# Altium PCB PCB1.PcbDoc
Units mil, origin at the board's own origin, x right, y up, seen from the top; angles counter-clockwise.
Board outline 984.25 x 984.25 mil, 2 copper layers (Top Layer, Bottom Layer); 59 components, 54 nets, 230 pads, 136 vias.
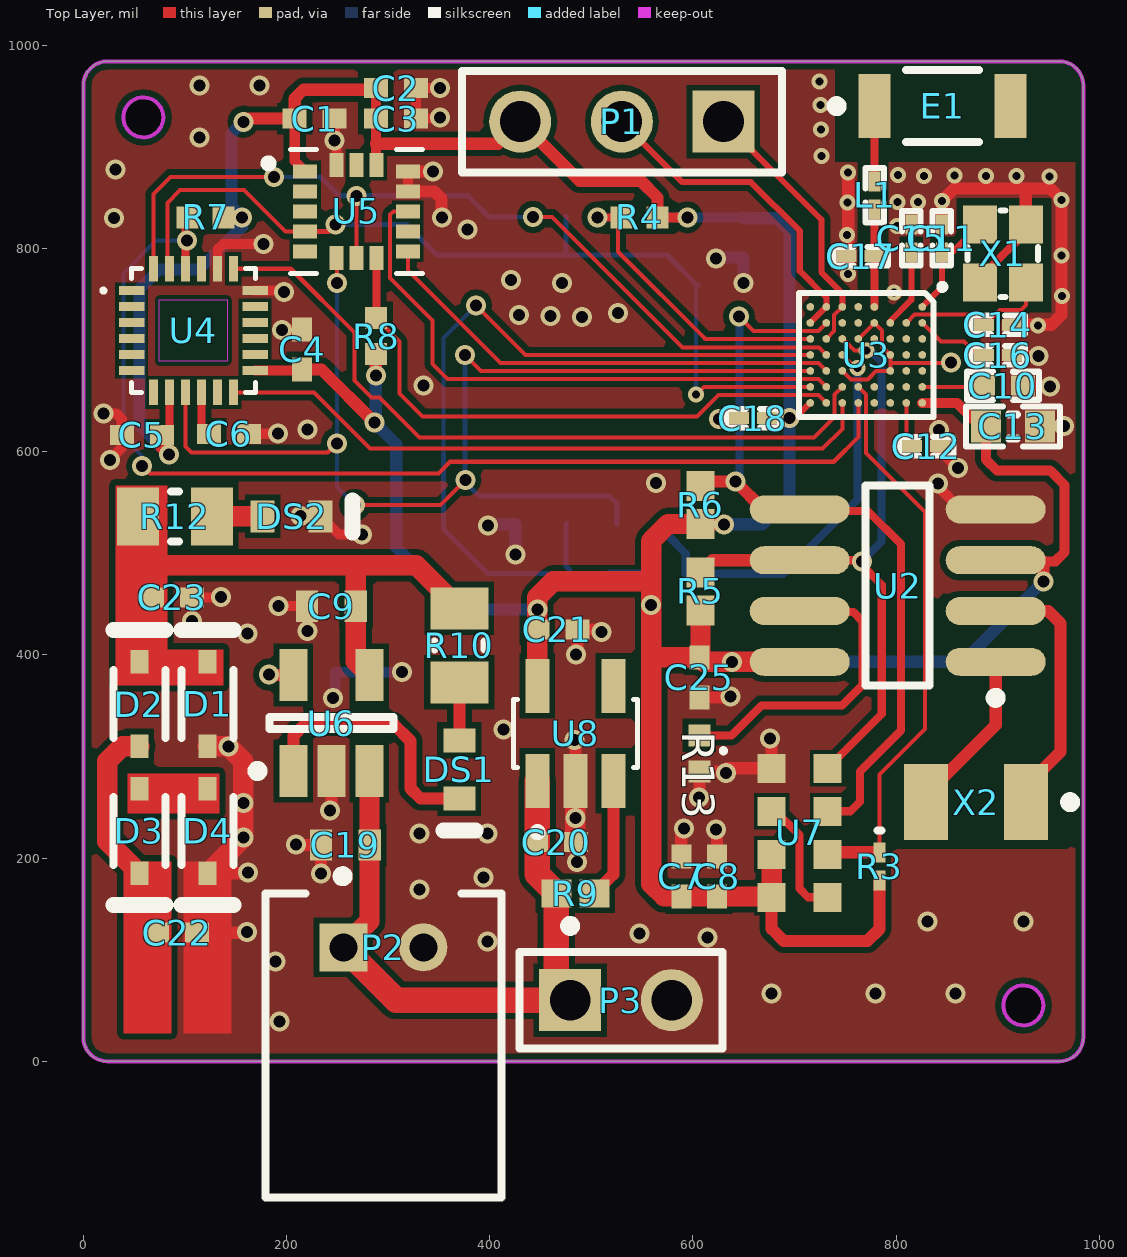
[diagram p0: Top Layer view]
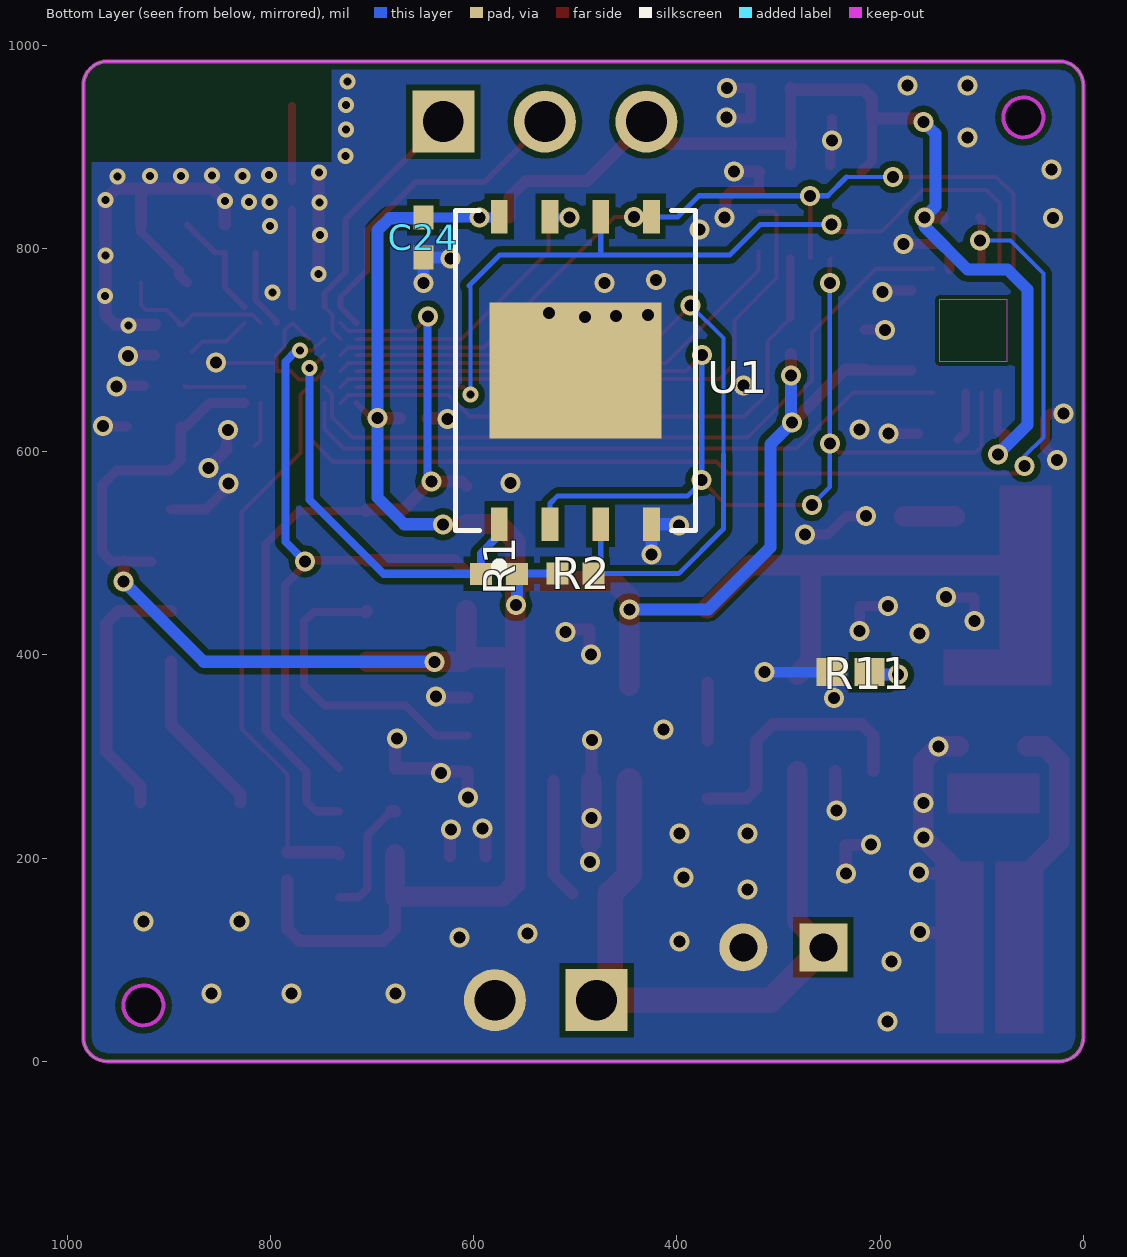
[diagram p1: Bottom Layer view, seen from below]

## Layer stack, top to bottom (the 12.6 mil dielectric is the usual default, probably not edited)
Top Solder: solder mask 0.4, Solder Resist, Dk 3.5
Top Layer: signal copper 1.4
Dielectric1: dielectric 12.6, FR-4, Dk 4.8
Bottom Layer: signal copper 1.4
Bottom Solder: solder mask 0.4, Solder Resist, Dk 3.5

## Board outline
0,23.62 0,960.63 cw(c23.62,960.63) 23.62,984.25 960.63,984.25 cw(c960.63,960.63) 984.25,960.63 984.25,23.62 cw(c960.63,23.62) 960.63,0 23.62,0 cw(c23.62,23.62)
cut-out: 905.51,55.12 ccw(c925.2,55.12) 925.2,35.43 ccw(c925.2,55.12) 944.88,55.12 ccw(c925.2,55.12) 925.2,74.8 ccw(c925.2,55.12)
cut-out: 59.06,909.45 cw(c59.06,929.13) 39.37,929.13 cw(c59.06,929.13) 59.06,948.82 cw(c59.06,929.13) 78.74,929.13 cw(c59.06,929.13)

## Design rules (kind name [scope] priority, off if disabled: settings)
Clearance Clearance_1 [InComponentClass('p')] p1: gap=3.94
Clearance [All] p2: gap=5.91
PolygonConnect [All] p1: connectstyle=Direct reliefconductorwidth=10 reliefentries=4 polygonreliefangle="90 Angle" airgapwidth=10
RoutingVias [All] p1: holewidth=11.81 width=19.68 viastyle="Through Hole" minholewidth=11.81 minwidth=19.68 maxholewidth=11.81 maxwidth=19.68
SilkToSolderMaskClearance SilkscreenOverComponentPads [IsPad] p1: minsilkscreentomaskgap=10 clearancetoexposedcopper=TRUE
SolderMaskExpansion [All] p1: expansion=4
Width [All] p1: maxlimit=1000 minlimit=4 preferedwidth=10
29 further rules are at their usual default settings.

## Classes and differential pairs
component class p: U3 U4 U5 U7
component class "SimPL_IMU_v1_1 _OCT31(2)": C10 C11 C12 C13 C14 C15 C16 C17 C18 C24 C25 C? E1 L1 P1 R1 R2 R4 R5 R6 R13 U1 U2 U3 X1 X2
component class "SimPL_IMU_v1_0 _OCT31(2)": C1 C2 C3 C4 C5 C6 C7 C8 C9 C19 C20 C21 C22 C23 D1 D2 D3 D4 DS1 DS2 P2 P3 R3 R7 R8 R9 R10 R11 R12 U4 U5 U6 U7 U8

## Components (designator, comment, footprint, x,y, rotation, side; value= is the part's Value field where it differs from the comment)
C1 "0.1uF" 0402 227.72,927.87 r0 top
C2 "0.1uF" 0402 307.72,957.87 r0 top
C3 "1.0uF" 0402 307.72,927.87 r0 top
C4 "0.1uF" 0402 215.39,700.79 r90 top
C5 "0.1uF" 0402 57.48,616.54 r180 top
C6 "0.1uF" 0402 143.31,617.72 r0 top
C7 "0.1uF" 0402 588.52,181.99 r90 top
C8 "2.2uF" 0402 623.52,181.99 r90 top
C9 "4.7uF" CAPC1005X65X10ML15 244.17,448.03 r0 top
C10 "1.0µF" CAPC1005X04L 905,665 r180 top
C11 "12pF" CAPC0603X03L 845,810 r270 top
C12 "100nF" CAPC0603X03L 829.53,605.51 r0 top
C13 "4.7µF" CAPC1608X06L 915,625 r0 top
C14 "12pF" CAPC0603X03L 900,725 r180 top
C15 "100pF" CAPC0603X03L 815,810 r90 top
C16 "100pF" CAPC0603X03L 900,695 r180 top
C17 "1.0pF" CAPC0603X03L 764.96,792.52 r0 top
C18 "100nF" CAPC0603X03L 659.06,633.07 r180 top
C19 "4.7uF" CAPC1005X65X10ML15 257.87,212.99 r0 top
C20 "1uF" 0402 465.35,215.75 r0 top
C21 "1uF" 0402 466.54,425.2 r0 top
C22 "6.8nF" 0402 92.4,126.65 r0 top
C23 "220uF" 0402 87.4,456.65 r0 top
C24 "1.0uF" 0402 649.61,811.02 r270 bottom
C25 "2.2uF" 0402 606.3,377.95 r270 top
D1 "1N4148WS" DIOD-SOD323-2-A_V 122.4,351.65 r90 top
D2 "1N4148WS" DIOD-SOD323-2-A_V 55.16,351.65 r90 top
D3 "1N4148WS" DIOD-SOD323-2-A_V 55.16,226.77 r270 top
D4 "1N4148WS" DIOD-SOD323-2-A_V 122.4,226.65 r270 top
DS1 "red LED" VISH-TLMS1000_V 370.08,287.4 r270 top
DS2 "red LED" VISH-TLMS1000_V 205,536.5 r0 top
E1 "2450AT18A100E" JT-2450AT18A100-2_V 845.67,940.16 r0 top
L1 "3.3nH" INDC0603X03L 778.74,852.36 r90 top
P1 "3pin header" SMTC-TSW-103-07-X-S 630,925 r180 top
P2 "Battery Header" JST-S2B-PH-K-S_V 295.28,15.75 r0 top
P3 "2pin header" AMPH-68000-102HLF_V 529.13,60.24 r0 top
R1 "10k" RESC1005X40X25NL05T05 575.2,479.92 r180 bottom
R2 "10k" RESC1005X40X25NL05T05 500,480 r0 bottom
R3 "8.2k" 0603 783.52,191.99 r270 top
R4 "10k" RESC1005X40X25NL05T05 547.24,830.71 r0 top
R5 "2.2K" RESC1005X40X25ML10T10 607.36,462.64 r270 top
R6 "2.2K" RESC1005X40X25ML10T10 607.36,547.64 r270 top
R7 "10k" RESC1005X40X25NL05T05 120.39,830.79 r0 top
R8 "10k" RESC1005X40X25NL05T05 288.19,713.78 r270 top
R9 "2.2K" RESC1005X40X25ML10T10 484.25,165.35 r180 top
R10 "330" RESC2013X50X30NL20T20 370.08,409.45 r90 top
R11 "2.2K" RESC1005X40X25ML10T10 229.17,383.03 r180 bottom
R12 "330" RESC2013X50X30NL20T20 90,536.5 r180 top
R13 "1k" RESC1005X40X25NL05T05 606.3,303.15 r90 top
U1 "MT25QL256ABA1EW9-0SIT" *SON127P600X800X80-9N 500,680 r90 bottom
U2 "DS1388Z-33+T&R" S8+4_M 801.54,468.23 r180 top
U3 "nRF52832-CIAA" BGA50C40P7X8_295X322X50 770.63,695.35 r270 top
U4 "ICM-20649" *QFN40P300X300X95-24N 108.27,719.29 r0 top
U5 "ADXL372BCCZ-RL7" *PQFN50P322X300X114-16N 268.78,836.57 r0 top
U6 "MCP73831T-2ATI/OT" SOT-23-OT5_M 244.17,333.03 r90 top
U7 "VCNL4040M3OE" *VISHAY_VCNL4040_4X2X1.1 705,225 r0 top
U8 "AP2112K-3.3TRG1" *SOT95P285X140-5N 484.25,322.83 r90 top
X1 "32MHz" BT-XTAL_2016 905,795 r90 top
X2 "32.768KHz-T" ABRA-ABS07-2_V 878.74,255.12 r180 top

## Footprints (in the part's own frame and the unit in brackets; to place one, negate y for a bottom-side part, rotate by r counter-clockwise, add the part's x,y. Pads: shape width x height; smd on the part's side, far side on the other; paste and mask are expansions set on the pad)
0402 [mm] "Chip Capacitor, Body 1.0x0.5mm, IPC High Density"
  rect 0.6x0.5 smd: 1(-0.5,0) 2(0.5,0)
  body extent -0.55,-0.3 0.55,0.3, height 1.3
0603 [mm] "Chip Inductor, Body 0.6x0.3mm, IPC High Density"
  rect 0.5x0.3 smd: 1(-0.35,0) 2(0.35,0)
  silkscreen extent -0.9,-0.05 -0.9,0.05, body extent -0.33,-0.18 0.33,0.18, height 0.55
*PQFN50P322X300X114-16N [mm]
  rect 0.6x0.35 smd: 1(-1.285,1) 2(-1.285,0.5) 3(-1.285,0) 4(-1.285,-0.5) 5(-1.285,-1) 9(1.285,-1) 10(1.285,-0.5) 11(1.285,0) 12(1.285,0.5) 13(1.285,1)
  rect 0.35x0.6 smd: 6(-0.5,-1.165) 7(0,-1.165) 8(0.5,-1.165) 14(0.5,1.165) 15(0,1.165) 16(-0.5,1.165)
  silkscreen extent -2.3,-1.55 1.65,1.55
*QFN40P300X300X95-24N [mm]
  rect 0.64x0.22 smd: 1(-1.545,1) 2(-1.545,0.6) 3(-1.545,0.2) 4(-1.545,-0.2) 5(-1.545,-0.6) 6(-1.545,-1) 13(1.545,-1) 14(1.545,-0.6) 15(1.545,-0.2) 16(1.545,0.2) 17(1.545,0.6) 18(1.545,1)
  rect 0.22x0.64 smd: 7(-1,-1.545) 8(-0.6,-1.545) 9(-0.2,-1.545) 10(0.2,-1.545) 11(0.6,-1.545) 12(1,-1.545) 19(1,1.545) 20(0.6,1.545) 21(0.2,1.545) 22(-0.2,1.545) 23(-0.6,1.545) 24(-1,1.545)
  Keep-Out Layer region: -0.85,0.77 0.85,0.77 0.85,-0.77 -0.85,-0.77
  Keep-Out Layer region: -0.85,0.77 0.85,0.77 0.85,-0.77 -0.85,-0.77
  Keep-Out Layer region: -0.85,0.77 0.85,0.77 0.85,-0.77 -0.85,-0.77
  Keep-Out Layer region: -0.85,0.77 0.85,0.77 0.85,-0.77 -0.85,-0.77
  Keep-Out Layer region: -0.85,0.77 0.85,0.77 0.85,-0.77 -0.85,-0.77
  Keep-Out Layer region: -0.85,0.77 0.85,0.77 0.85,-0.77 -0.85,-0.77
  silkscreen extent -2.3,-1.55 1.55,1.55
*SON127P600X800X80-9N [mm]
  rect 0.84x0.42 smd: 1(-3.845,1.905) 2(-3.845,0.635) 3(-3.845,-0.635) 4(-3.845,-1.905) 5(3.845,-1.905) 6(3.845,-0.635) 7(3.845,0.635) 8(3.845,1.905)
  rect 3.4x4.3 smd: 9(0,0)
  silkscreen extent -4.99,-3 4,3
*SOT95P285X140-5N [mm]
  rect 1.35x0.6 smd: 1(-1.185,0.95) 2(-1.185,0) 3(-1.185,-0.95) 4(1.185,-0.95) 5(1.185,0.95)
  silkscreen extent -2.57,-1.55 0.85,1.55
*VISHAY_VCNL4040_4X2X1.1 [mm]
  rect 0.7x0.725 smd: 1(-0.7,1.613) 2(-0.7,0.537) 3(-0.7,-0.537) 4(-0.7,-1.613) 5(0.7,-1.613) 6(0.7,-0.537) 7(0.7,0.537) 8(0.7,1.613)
  silkscreen extent -1.96,2 -1.86,2.1
ABRA-ABS07-2_V [mm] "Hand Drawn, 2-Leads, Body 3.2x1.5mm, Pitch 2.5mm"
  rect 1.1x1.9 smd: 1(-1.25,0) 2(1.25,0)
  silkscreen extent -2.48,-0.12 -2.23,0.12, body extent -1.6,-0.75 1.6,0.75, height 0.9
AMPH-68000-102HLF_V [mm] "THD, 2-Leads, Body 5.08x2.41mm, Pitch 2.54mm"
  rect 1.55x1.55 hole 1.02: 1(-1.27,0)
  round 1.55 hole 1.02: 2(1.27,0)
  silkscreen extent -2.54,-1.2 2.54,1.98, body extent -2.54,-1.2 2.54,1.2, height 8.38
BGA50C40P7X8_295X322X50 [mm]
  round 0.193 smd: A1(-1.2,1.4) A2(-0.8,1.4) A3(-0.4,1.4) A4(0,1.4) A5(0.4,1.4) A6(0.8,1.4) A7(1.2,1.4) B2(-0.8,1) B3(-0.4,1) B4(0,1) B5(0.4,1) B6(0.8,1) B7(1.2,1) C2(-0.8,0.6) C3(-0.4,0.6) C4(0,0.6) C5(0.4,0.6) C6(0.8,0.6) C7(1.2,0.6) D1(-1.2,0.2) D2(-0.8,0.2) D3(-0.4,0.2) D6(0.8,0.2) D7(1.2,0.2) E1(-1.2,-0.2) E2(-0.8,-0.2) E3(-0.4,-0.2) E6(0.8,-0.2) E7(1.2,-0.2) F1(-1.2,-0.6) F2(-0.8,-0.6) F3(-0.4,-0.6) F4(0,-0.6) F5(0.4,-0.6) F6(0.8,-0.6) F7(1.2,-0.6) G1(-1.2,-1) G2(-0.8,-1) G3(-0.4,-1) G4(0,-1) G5(0.4,-1) G6(0.8,-1) G7(1.2,-1) H1(-1.2,-1.4) H2(-0.8,-1.4) H3(-0.4,-1.4) H4(0,-1.4) H5(0.4,-1.4) H6(0.8,-1.4) H7(1.2,-1.4)
  silkscreen extent -1.75,-1.69 1.55,1.95, body extent -1.48,-1.61 1.48,1.61, height 0.51
BT-XTAL_2016 [mm]
  rect 0.95x0.85 smd: 1(-0.725,-0.575) 2(0.725,-0.575) 3(0.725,0.575) 4(-0.725,0.575)
  silkscreen extent -1.08,-0.88 1.08,0.88, body extent -1.05,-0.85 1.05,0.85, height 0.56
CAPC0603X03L [mm]
  rect 0.5x0.3 smd: 1(-0.35,0) 2(0.35,0)
  silkscreen extent -0.68,-0.23 0.68,0.23, body extent -0.3,-0.15 0.3,0.15, height 0.3
CAPC1005X04L [mm]
  rect 0.6x0.5 smd: 1(-0.5,0) 2(0.5,0)
  silkscreen extent -0.9,-0.35 0.9,0.35, body extent -0.51,-0.25 0.51,0.25, height 0.5
CAPC1005X65X10ML15 [mm] "Chip Capacitor, 2-Leads, Body 1.15x0.65mm, IPC Low Density"
  rect 0.56x0.78 smd: 1(-0.61,0) 2(0.61,0)
  body extent -0.57,-0.33 0.58,0.32, height 0.65
CAPC1608X06L [mm]
  rect 0.75x0.8 smd: 1(-0.675,0) 2(0.675,0)
  silkscreen extent -1.17,-0.5 1.17,0.5, body extent -0.8,-0.43 0.8,0.43, height 0.8
DIOD-SOD323-2-A_V [mm] "SOD-323, 2-Leads, Body 1.7x1.3mm"
  rect 0.59x0.45 smd: 1(-1.055,0) 2(1.055,0)
  silkscreen extent -0.85,-0.65 1.85,0.65, body extent -0.85,-0.65 0.85,0.65, height 1.2
INDC0603X03L [mm]
  rect 0.5x0.3 smd: 1(-0.35,0) 2(0.35,0)
  silkscreen extent -0.68,-0.23 0.68,0.23, body extent -0.31,-0.16 0.31,0.16, height 0.26
JST-S2B-PH-K-S_V [mm] "THD, 2-Leads, Body 7.6x5.9mm, Pitch 2mm"
  rect 1.2x1.2 hole 0.7: 1(-1,2.45)
  round 1.2 hole 0.7: 2(1,2.45)
  silkscreen extent -2.95,-3.8 2.95,4.35, body extent -2.95,-3.8 2.95,3.8, height 4.8
JT-2450AT18A100-2_V [mm] "Chip Antenna, 2-Leads, Body 3.4x1.8mm"
  rect 0.8x1.6 smd: 1(-1.7,0) 2(1.7,0)
  silkscreen extent -2.77,-0.9 0.91,0.9, body extent -1.7,-0.9 1.7,0.9, height 1.4
RESC1005X40X25ML10T10 [mm] "Chip Resistor, 2-Leads, Body 1.00x0.50mm, IPC Low Density"
  rect 0.75x0.7 smd: 1(-0.475,0) 2(0.475,0)
  body extent -0.55,-0.3 0.55,0.3, height 0.4
RESC1005X40X25NL05T05 [mm] "Chip Resistor, 2-Leads, Body 1.05x0.55mm, IPC Medium Density"
  rect 0.55x0.55 smd: 1(-0.45,0) 2(0.45,0)
  body extent -0.53,-0.28 0.53,0.28, height 0.4
RESC2013X50X30NL20T20 [mm] "Chip Resistor, 2-Leads, Body 2.00x1.25mm, IPC Medium Density"
  rect 1.05x1.45 smd: 1(-0.925,0) 2(0.925,0)
  silkscreen extent -0.1,-0.63 0.1,0.63, body extent -1.1,-0.72 1.1,0.72, height 0.5
S8+4_M [mm] "SOIC, 8-Leads, Body 4.9x3.9mm, Pitch 1.27mm, IPC Low Density"
  oval 2.5x0.7 smd: 1(-2.45,1.905) 2(-2.45,0.635) 3(-2.45,-0.635) 4(-2.45,-1.905) 5(2.45,-1.905) 6(2.45,-0.635) 7(2.45,0.635) 8(2.45,1.905)
  silkscreen extent -2.58,-2.5 0.8,2.93, body extent -2,-2.5 2,2.5, height 1.75
SMTC-TSW-103-07-X-S [mm] ".025 SQ Post Terminal Strip Assembly, 1x3 Pins, Vertical, 2.54mm Pitch, Male"
  rect 1.55x1.55 hole 1.02: 1(0,0)
  round 1.55 hole 1.02: 2(2.54,0) 3(5.08,0)
  silkscreen extent -1.46,-1.27 6.54,1.27, body extent -1.27,-1.27 6.35,1.27, height 8.38
SOT-23-OT5_M [mm] "SOT23, 5-Leads, Body 2.9x1.7mm, Pitch 0.95mm, Lead Span 2.8mm, IPC Low Density"
  rect 1.3x0.7 smd: 1(-1.2,0.95) 2(-1.2,0) 3(-1.2,-0.95) 4(1.2,-0.95) 5(1.2,0.95)
  silkscreen extent -1.32,-1.55 0.15,1.97, body extent -0.9,-1.55 0.9,1.55, height 1.45
VISH-TLMS1000_V [mm] "SMD, 2-Leads, Body 0.8x1.6mm"
  rect 0.6x0.8 smd: 1(-0.725,0) 2(0.725,0)
  silkscreen extent 1.52,-0.4 1.52,0.4, body extent -0.8,-0.4 0.8,0.4, height 0.65

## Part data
C1 C2 C4 C5 C6 C7 C8 C20 C21 C22 C23 C25: library part 0.1UF-0402-16V-10%, "0.1?μF ceramic capacitors    A capacitor is a passive two-terminal electrical component used to store electrical energy temporarily in an electric field."
C3: library part 1.0UF-0402-16V-10%, "1?μF ceramic capacitors    A capacitor is a passive two-terminal electrical component used to store electrical energy temporarily in an electric field."
C9 C19: library part CMP-2000-05438-1, "Chip Capacitor, 4.7 uF, +/- 20%, 10 V, -55 to 85 degC, 0402 (1005 Metric), RoHS, Tape and Reel"
C10: library part C0402-1μ0, "Capacitor, X5R, ±5%"
C11 C14: library part C0201-12p, "Capacitor, NP0, ±2%"
C12 C18: library part C0201-100n, "Capacitor, X7R, ±10%"
C13: library part C0603-4μ7, "Capacitor, X5R, ±10%"
C15 C16: library part C0201-100p, "Capacitor, NP0, ±5%"
C17: library part C0201-1.0p, "Capacitor, NP0, ±5%"
C24: library part 1.0UF-0402-16V-10%, "1?"
D1 D2 D3 D4: library part CMP-1667-00004-1, "Fast Switching Diode, 75 V, 0.3 A, -65 to 150 degC, 2-Pin SOD323, RoHS, Tape and Reel"
DS1 DS2: library part CMP-2000-07254-1, "Low Current LED, 40 mW, 1.8 V, -40 to 100 degC, 2-Pin SMD (0603), RoHS, Tape and Reel"
E1: library part CMP-2000-05167-1, "Ceramic Antenna, 2.45 GHZ, 2 W, -40 to 125 degC, 2-Pin SMD, RoHS, Tape and Reel"
L1: library part L0201-3n3, "High frequency chip inductor ±5%"
P1: library part CMP-1024-00331-1, "0.025\" SQ Post Header, Through-hole, Vertical, -55 to 125 degC, 2.54 mm Pitch, 3-Pin, Male, RoHS"
P2: library part CMP-1755-00004-1, "Male Header, Pitch 2 mm, 1 x 2 Position, Height 4.8 mm, Tail Length 3.4 mm, -25 to 85 degC, RoHS, Bulk"
P3: library part CMP-2000-05666-1, "Male Header, Pitch 2.54 mm, 1 x 2 Position, Height 8.38 mm, Tail Length 2.41 mm, RoHS, Bulk"
R1 R2 R4 R7 R8: library part CMP-2002-00607-3, "Chip Resistor, 10 KOhm, +/- 1%, 100 mW, -55 to 155 degC, 0402 (1005 Metric), RoHS, Tape and Reel"
R3: library part 8.2KOHM-0603-1/10W-5%, "8.2k?? resistor    A resistor is a passive two-terminal electrical component that implements electrical resistance as a circuit element. Resistors act to reduce current flow, and, at the same time, act to lower voltage levels within circuits. - Wikipedia"
R5 R6 R9 R11: library part CMP-2002-06097-1
R10 R12: library part CMP-2001-03823-1
R13: library part CMP-2002-08276-1
U1: "NOR Flash Serial-SPI 3.3V 256Mbit 256M x 1bit 8-Pin WPDFN"
U2: library part CMP-0254-00385-1, "I2C Real-Time Clock/Supervisor with Trickle Charger and 512 Byte EEPROM, 3.3V, 8-Pin SO, -40 to 85 degC, Pb-Free, Reel"
U3: "Multi-protocol Bluetooth Low Energy, ANT and 2.4GHz proprietary system-on-chip"
U4: "Wide-Range 6-Axis MEMS MotionTracking Device for Sports and High Impact Applications"
U5: "Accelerometer Triple ?±200g 2.5V 16-Pin LGA T/R"
U6: library part CMP-0133-00144-1, "Miniature Single-Cell, Fully Integrated Li-Ion, Li-Polymer Charge Management Controller, 4.2V, 5-Pin SOT-23, Industrial Temperature, Tape and Reel"
U7: "VCNL4040 Series 3.6 V 200 mm 16 Bit I2C SMT Proximity and Ambient Light Sensor"
U8: "AP2112 Series 0.6 A 3.3 V Fixed Output SMT LDO Linear Regulator - SOT23-5"
X1: library part XTAL_SMD2016_32MHz_8pF_Epson, "XTAL SMD 2016, 32MHz, Cl=8pF, Total Tol: ±40ppm"
X2: library part CMP-0447-00001-2, "Crystal, 32.768 kHz, 12.5 pF, -40 to 85 degC, SMD Low Profile 3.2 x 1.5 x 0.9 mm, Tape and Reel"

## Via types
v1: diameter 19.68, hole 11.81, Top Layer to Bottom Layer, tented both sides, 110 vias
v2: diameter 15.75, hole 7.87, Top Layer to Bottom Layer, tented both sides, 26 vias

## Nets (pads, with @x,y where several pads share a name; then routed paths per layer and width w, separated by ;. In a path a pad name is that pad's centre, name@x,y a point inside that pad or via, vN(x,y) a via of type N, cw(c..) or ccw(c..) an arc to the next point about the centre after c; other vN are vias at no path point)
+3V3: C1.1 C2.1 C3.1 C4.1 C5.1 C7.1 C8.1 C13.1 C18.1 C21.1 C24.1 C25.1 P1.3 R1.2 R2.2 R3.2 R4.2 R5.2 R6.2 R7.2 R8.2 U1.8 U2.3 U2.8 U3.A7 U3.H7 U4.8 U4.13 U5.1 U5.14 U7.3 U7.4 U8.5 | length 4092.6
  Top Layer w6: v1@700.47,633.07 U3.H7
  Top Layer w8: C5.1@77.17,612.99 84.65,620.47 U4.8
  Top Layer w10: U4.13 214.21,679.92 C4.1 ; C1.1 208.03,886.1 U5.1 ; C2.1 C3.1 288.03,903.15 288.03,882.87 U5.14 ; R4.2 v1(594.49,830.71) ; v1(694.88,633.07) v1@700.47,633.07 ; U3.A7 859.76,648.11 882.87,625 C13.1 888.43,592.28 899.21,581.5 951.57,581.5 965.75,567.32 965.75,501.18 956.69,492.13 944.88,492.13 U2.3@917.32,492.13
  Top Layer w12: C5.1 77.17,612.99 77.17,604.33 v1(84.25,597.24) ; R7.2 156.22,830.79 v1(156.3,830.71) ; v1(157.48,924.8) 160.55,927.87 C1.1 208.03,947.8 216.54,956.3 286.46,956.3 C2.1 ; C4.1 234.25,681.1 v1(286.61,628.74) ; v1(287.8,675.2) 287.8,695.67 R8.2 ; 288.03,903.15 408.15,903.15 P1.3 488.46,866.54 548.82,866.54 564.96,850.39 R4.2 ; R6.2 607.68,528.62 v1(630.32,528.62) ; C18.1 v1(694.88,633.07) ; U7.4 677.44,130.43 689.37,118.5 771.65,118.5 783.52,130.37 R3.2 ; v1(944.88,472.44) U2.3@944.88,492.13
  Top Layer w20: U8.5 C21.1 v1(446.85,444.88) 446.85,456.69 462.6,472.44 559.06,472.44 ; R5.2 607.36,398.7 C25.1 ; R6.2 575.79,528.94 559.06,512.2 559.06,472.44 ; U7.3 U7.4 676.65,162.3 C8.1 C7.1 571.55,162.3 559.06,174.8 559.06,393.7 ; U2.8 v1(638.58,393.23) 610.71,393.23 C25.1 ; 559.06,393.7 559.06,472.44 ; 559.06,393.7 562.99,397.64 C25.1
  Bottom Layer w8: R2.2 557.4,480 R1.2
  Bottom Layer w10: U1.8 575.67,830.71 C24.1
  Bottom Layer w12: v1(84.25,597.24) 55.12,626.38 55.12,759.84 74.8,779.53 114.17,779.53 156.3,821.65 v1(156.3,830.71) 145.67,841.34 145.67,912.99 v1(157.48,924.8) ; v1(287.8,675.2) 287.8,629.92 v1(286.61,628.74) 307.87,607.48 307.87,505.91 368.9,444.88 v1(446.85,444.88) ; R1.2 557.48,450.17 v1(558.59,449.06) ; v1(630.32,528.62) 668.39,528.62 694.88,555.12 v1(694.88,633.07) 694.88,817.72 682.68,829.92 650.39,829.92 C24.1 ; v1(638.58,393.23) 865.67,393.23 v1(944.88,472.44)
ACCEL_CS: R8.1 U3.G7 U5.8 | length 584.4
  Top Layer w4: R8.1 311.02,708.66 311.02,657.48 333.86,634.65 603.77,634.65 625.03,655.91 723.46,655.91 U3.G7
  Top Layer w8: R8.1@288.46,731.5 U5.8
ACCEL_INT1: U3.G6 U5.11 | length 580
  Top Layer w4: U5.11 305.08,836.57 301.97,833.46 301.97,770.87 343.5,729.33 343.5,686.42 358.27,671.65 723.46,671.65 U3.G6
ACCEL_INT2: U3.G5 U5.9 | length 471.5
  Top Layer w4: U5.9 319.72,796.85 319.72,778.31 410.63,687.4 723.46,687.4 U3.G5
CATHODE: U7.2 U7.5 | length 121.1
  Top Layer w8: U7.2@681.4,246.16 704.72,222.83 704.72,170.08 713.29,161.52 U7.5
  Top Layer w12: U7.2 U7.2@681.4,246.16
COIL1: C22.1 D2.1 D3.2 | length 160.8
  Top Layer w20: D3.2 23.62,216.77 23.62,295.28 38.46,310.12 D2.1
CS_MEM: R1.1 U1.1 U3.F4 | length 405.5
  Top Layer w4: U3.F4 760.08,682.28 760.47,682.68 v2(761.81,682.68)
  Bottom Layer w8: U1.1 575,517.91 592.91,500 R1.1 688.98,479.92 761.81,552.76 v2(761.81,682.68)
DEC1: C12.1 U3.B7 | length 45
  Top Layer w4: U3.B7 810,611.26 C12.1
DEC2: C16.2 U3.A2 | length 63.7
  Top Layer w4: U3.A2 843.94,708.66 866.93,708.66 C16.2@877.56,698.03
DEC3: C15.1 U3.C2 | length 78
  Top Layer w6: U3.C2 794.25,728.68 815,749.43 C15.1
DEC4: C10.2 U3.A6 | length 60
  Top Layer w4: U3.A6 884.17,663.86 C10.2
GND: C1.2 C2.2 C3.2 C4.2 C5.2 C6.2 C7.2 C8.2 C9.1 C10.1 C11.1 C12.2 C13.2 C14.1 C15.2 C16.1 C17.1 C18.2 C19.1 C20.2 C21.2 C22.2 C23.2 C24.2 C25.2 D1.1 D4.2 DS2.2 P2.2 P3.2 R11.1 R13.1 U1.4 U1.9 U2.4 U3.C4 U3.C5 U3.D2 U3.E3 U3.F5 U4.18 U4.20 U5.12 U5.13 U5.16 U6.2 U7.1 U8.2 X1.2 X1.4 | length 2470.9
  Top Layer w4: U3.F5 755.35,671.26 772.05,671.26 780.39,679.61 U3.C5 794.25,687.28 853.42,687.28 v1(853.94,687.8) ; U3.E3 U3.D2 786.22,719.13 786.22,703.39 U3.C4 794.25,687.8
  Top Layer w5: C14.1@912.99,724.21 C14.1
  Top Layer w8: X1.4@890.16,778.74 X1.2@927.64,816.22
  Top Layer w10: v1(19.68,637.8) 32.28,637.8 37.8,632.28 C5.2 37.8,603.94 v1(25.98,592.13) ; v1(107.09,433.46) C23.2 135,456.65 v1(135.43,457.09) ; U4.20 131.89,798.82 137.4,804.33 v1(177.17,804.33) ; C6.2 191.34,617.72 v1(191.73,618.11) ; U4.18 196.46,758.66 v1(197.64,757.48) ; v1(192.13,448.43) 192.52,448.03 C9.1 220.16,423.94 v1(220.47,423.62) ; v1(195.28,719.68) 196.06,720.47 C4.2 ; v1(213.78,536.61) 213.9,536.5 DS2.2 251.54,518.5 v1(274.02,518.5) ; C1.2 v1(247.4,906.54) 249.09,904.84 U5.16 ; U5.12 U5.13 ; v1(350.79,958.27) 350.39,957.87 C2.2 C3.2 349.92,927.87 v1(351.18,929.13) ; v1(841.34,568.9) 840.94,568.5 840.94,566.14 863.86,543.23 U2.4 ; v1(842.13,621.65) 843.31,620.47 C12.2 ; X1.4 890.16,774.25 X1.4@890.16,778.74 ; C16.1 939.65,695 v1(940.16,694.49) ; C10.1 950.75,665 v1(951.57,664.17) ; X1.2@927.64,816.22 X1.2 ; C13.2 964.76,625 v1(964.96,625.2)
  Top Layer w12: C22.2 160.12,126.65 v1(161.02,127.56) ; D4.2 161.1,185.12 v1(161.81,185.83) ; v1(209.06,213.39) 209.45,212.99 C19.1 v1(233.86,185.04) ; v1(242.91,246.85) 244.17,248.11 U6.2 ; U5.12 345.32,856.26 352.36,849.21 352.36,831.5 v1(353.15,830.71) ; U5.13 344.06,875.94 v1(344.09,875.98) ; v1(483.46,316.14) 484.25,315.35 U8.2 ; v1(484.65,400.39) 484.25,400.79 484.25,401.57 486.22,403.54 C21.2 507.48,425.2 v1(509.84,422.83) ; C20.2 485.04,196.85 v1(485.83,196.06) ; C7.2 588.52,226.32 v1(591.34,229.13) ; v1(605.91,259.84) 606.3,260.24 R13.1 v1@630.71,285.43 ; C25.2 636.22,358.27 v1(637.01,359.06) ; v1(622.44,228.35) 623.52,227.26 C8.2 ; v1(625.7,632.35) v1@627.49,632.35 ; v1@630.71,633.07 C18.2 ; v1(632.28,283.86) v1@630.71,285.43 ; v1(675.59,317.72) 677.44,315.87 U7.1 633.76,288.48 v1@630.71,285.43 ; v2(752.36,874.8) 752.76,874.41 v2(752.76,774.8) ; C12.2 843.31,601.97 v1(861.02,584.25) ; C11.1 v2(845,846.97) 857.09,859.06 925.98,859.06 ; C14.1 952.95,725 962.6,734.65 v2(962.6,793.31) v2(962.6,848.03) 951.57,859.06 925.98,859.06 ; X1.2 927.64,857.4 925.98,859.06
  Top Layer w20: D4.2 v1(157.48,220.2) v1(157.48,254.33) 157.48,295.28 v1(142.64,310.12) D1.1 ; U8.2 v1(484.25,239.37) 484.25,216.54 C20.2
  Bottom Layer w10: v1(245.67,357.87) 247.87,360.08 R11.1 313.74,383.03 v1(313.78,383.07)
  Bottom Layer w12: v1(398.03,527.56) 399.09,528.62 U1.4 425,499.02 v1(425.2,498.82) ; v1(622.83,790.16) 624.02,791.34 C24.2 v1(649.61,766.14)
  other v1: 192.91,39.37 677.17,66.93 779.53,66.93 858.27,66.93 188.98,98.43 397.64,118.11 614.17,122.05 547.24,125.98 830.71,137.8 925.2,137.8 330.71,169.29 393.7,181.1 330.71,224.41 397.64,224.41 413.39,326.77 161.42,421.26 563.78,569.29 220.47,622.05 334.69,665.39 459.84,733.46 490.55,732.68 428.74,734.65 525.98,736.61 471.26,766.14 420.87,768.9 377.95,818.9 29.92,829.92 31.5,877.95 114.17,909.45 114.17,960.63 173.23,960.63
  other v2: 939.76,724.41 962.99,753.15 798.03,756.69 751.57,813.39 800.79,822.05 751.97,845.28 801.18,846.06 821.26,845.67 918.5,871.26 950.79,870.87 801.57,872.44 827.56,871.65 857.48,872.05 888.19,871.65 726.38,890.94 725.98,917.32 725.59,941.34 724.41,964.57
GYRO_CS: R7.1 U3.E7 U4.22 | length 1081.4
  Top Layer w4: v1(57.87,585.83) 64.96,578.74 349.61,578.74 361.02,590.16 738.58,590.16 762.76,614.33 U3.E7
  Top Layer w8: U4.22 100.39,828.5 R7.1
  Bottom Layer w4: v1(57.87,585.83) 57.87,595.67 39.37,614.17 39.37,775.59 71.65,807.87 v1(101.97,807.87)
GYRO_INT1: U3.F7 U4.12 | length 655.8
  Top Layer w4: U4.12 226.97,658.46 282.28,603.15 727.56,603.15 747.01,622.6 U3.F7
GYRO_INT2: U3.F6 U4.19 | length 733.2
  Top Layer w4: U4.19 204.13,780.12 266.93,717.32 266.93,670.08 283.46,653.54 291.34,653.54 ; 287.4,653.54 291.34,653.54 ; U3.F6 739.37,656.22 739.37,634.25 719.29,614.17 330.71,614.17 291.34,653.54
I2C_SCL: R5.1 U2.6 U3.F3 U7.8 | length 643.9
  Top Layer w4: U3.F3@748.03,710.63 759.06,699.61 v2(770.87,699.61)
  Top Layer w5: U3.F3 U3.F3@747.76,710.35
  Top Layer w8: U2.6 v1@761.5,493.23 ; U7.8 785.83,341.75 785.83,468.9 v1@764.37,490.35
  Top Layer w12: R5.1 619.25,493.23 U2.6
  Bottom Layer w8: v1(766.14,492.13) 785.43,511.42 785.43,688.58 774.41,699.61 v2(770.87,699.61)
I2C_SDA: R6.1 U2.5 U3.G2 U7.7 | length 790
  Top Layer w4: v1(645.28,733.07) 659.45,718.9 723.31,718.9 U3.G2
  Top Layer w8: U2.5@706.57,541.73 772.05,541.73 804.72,509.06 804.72,325.59 764.57,285.43 764.57,255.51 755.22,246.16 U7.7
  Top Layer w12: R6.1 611.89,570.87 v1(641.73,570.87) 669.37,543.23 U2.5 U2.5@706.57,541.73
  Bottom Layer w8: v1(641.73,570.87) 645.67,574.8 645.67,732.68 v1(645.28,733.07)
IR_INT: R3.1 U3.E6 U7.6 | length 555.6
  Top Layer w4: U3.E6 770.47,656.14 770.47,598.82 828.35,540.94 828.35,327.17 783.52,282.34 R3.1
  Top Layer w12: U7.6 734.49,205.77 R3.1
NetC6_1: C6.1 U4.10 | length 49.8
  Top Layer w8: U4.10 116.14,619.72 C6.1@123.98,611.89
NetC17_2: C17.2 L1.1 U3.D1 | length 96.1
  Top Layer w8: U3.D1 778.74,742.83 L1.1
NetD3_1: D3.1 D4.1
NetDS1_1: DS1.1 R10.1 | length 57.1
  Top Layer w12: DS1.1 R10.1
NetDS1_2: DS1.2 U6.1 | length 260.6
  Top Layer w12: U6.1 206.77,320.79 217.87,331.89 305.51,331.89 322.05,315.35 322.05,268.5 331.69,258.86 DS1.2
NetDS2_1: DS2.1 R12.1 | length 50
  Top Layer w20: R12.1 DS2.1
NetR9_1: R9.1 U8.3 | length 118.6
  Top Layer w12: R9.1 521.65,184.06 U8.3
NetR11_2: R11.2 U6.5 | length 53
  Top Layer w12: v1(182.68,380.71) 183.11,380.28 U6.5
  Bottom Layer w12: v1(182.68,380.71) 208.15,380.71 R11.2
NetR13_2: R13.2 U2.7 | length 309.8
  Top Layer w8: R13.2 637.8,320.87 667.32,350.39 746.85,350.39 766.93,370.47 766.93,433.07 757.87,442.13 U2.7@706.18,442.13
  Top Layer w12: U2.7 U2.7@706.18,442.13
NetU2_1: U2.1 X2.2 | length 166.5
  Top Layer w12: X2.2 829.53,262.6 897.99,331.06 U2.1
NetU2_2: U2.2 X2.1 | length 258.9
  Top Layer w12: U2.2 949.69,443.23 961.81,431.1 961.81,304.72 927.95,270.87 X2.1
P0.02/AIN0: U3.C6
P0.03/AIN1: U3.D6
P0.12: U1.6 U3.H6 U4.23 U5.4 | length 898.5
  Top Layer w4: U4.23 82.68,782.09 82.68,844.88 95.28,857.48 158.27,857.48 198.86,816.89 U5.4 ; v2(603.17,656.22) 610.81,663.86 U3.H6
  Top Layer w5: U5.4 241.3,816.89 v1(248.03,823.62)
  Bottom Layer w4: v2(603.17,656.22) 603.17,761.83 604.72,763.39
  Bottom Layer w5: v1(248.03,823.62) 318.11,823.62 348.03,793.7 474.8,793.7 ; U1.6 475,793.9 474.8,793.7 ; 604.72,763.39 574.41,793.7 474.8,793.7
P0.13: U1.5 U3.G4 U4.24 U5.7 | length 876.6
  Top Layer w4: U4.24 68.9,853.54 85.83,870.47 v1(187.4,870.47) ; U5.7 268.78,851.85 v1(268.9,851.97) ; v1(442.52,831.1) 461.42,831.1 589.76,702.76 723.86,702.76 U3.G4
  Bottom Layer w4: v1(187.4,870.47) 233.07,870.47 ; U1.5@425.28,831.1 v1(442.52,831.1)
  Bottom Layer w5: 233.07,870.47 251.57,851.97 v1(268.9,851.97) 378.35,851.97 399.21,831.1 U1.5@425.28,831.1
P0.14: U1.2 U3.H5 U4.9 U5.6 | length 1226.2
  Top Layer w4: U4.9 100.39,605.12 106.3,599.21 240.55,599.21 v1(249.61,608.27) ; U5.6@248.43,790.16 249.61,788.98 v1(249.61,766.14) ; v1(267.32,547.64) 351.57,547.64 v1(375.98,572.05) ; v1(375.59,695.28) 391.26,679.61 U3.H5
  Bottom Layer w4: v1(249.61,766.14) v1(249.61,608.27) 249.61,565.35 v1(267.32,547.64)
  Bottom Layer w5: v1@375.59,570.47 389.76,556.3 517.72,556.3 525,549.02 U1.2 ; v1@375.59,572.05 v1(375.59,695.28)
P0.15: R2.1 U1.3 U3.H4 | length 782.3
  Top Layer w4: v1(386.61,744.09) 435.35,695.35 U3.H4
  Bottom Layer w4: 354.33,597.24 354.33,711.81 v1(386.61,744.09) ; U1.3 474.8,528.82 U1.3@475.98,530
  Bottom Layer w5: 354.33,597.24 354.33,524.02 398.35,480 R2.1 475,487.28 U1.3
P0.16: R4.1 U1.7 U3.H3 | length 305.6
  Top Layer w4: R4.1@524.41,835.83 526.38,833.86 526.38,796.85 612.13,711.1 U3.H3
  Top Layer w8: v1(505.91,830.71) 519.29,830.71 R4.1@524.41,835.83
  Bottom Layer w8: v1(505.91,830.71) 522.76,830.71 524.41,832.36 525.2,831.57 U1.7
P0.17: P1.1 U3.F1 U3.G3 | length 268.9
  Top Layer w4: U3.G3 738.98,718.82 738.98,734.57 U3.F1
  Top Layer w6: P1.1 726.38,828.62 726.38,776.77 747.01,756.14 U3.F1
P0.18: P1.2 U3.G1 U3.H2 | length 327.5
  Top Layer w6: P1.2 589.65,865.35 657.09,865.35 705.12,817.32 705.12,777.95 731.26,751.81 U3.G1 U3.H2
P0.21: U3.H1
P0.22: U3.F2
P0.23: U3.E2
P0.24: U3.E1
P0.25: U3.B3
P0.26: U3.D3
P0.27: U3.B4
P0.28/AIN4: U3.A3
P0.29/AIN5: U3.A4
P0.30/AIN6: U3.A5
P0.31/AIN7: U3.B5
RF: E1.1 L1.2 | length 74
  Top Layer w8: L1.2 E1.1
VBAT: C19.2 C20.1 P2.1 P3.1 R9.2 U6.3 U8.1 | length 669.3
  Top Layer w20: P2.1 281.57,137.87 U6.3
  Top Layer w25: P2.1 308.11,60 P3.1@464.57,60 ; U8.1 446.85,184.06 R9.2 465.55,60.98 P3.1@464.57,60 ; P3.1@495,60 P3.1@464.57,60
VBUS: C9.2 C23.1 D1.2 D2.2 R10.2 R12.2 U6.4 | length 434.3
  Top Layer w20: 66.93,488.19 267.72,488.19 ; U6.4 268.19,393.66 C9.2 268.19,487.72 267.72,488.19 ; R10.2 327.76,488.19 267.72,488.19
XC1: C14.2 U3.B2 X1.1 | length 159.4
  Top Layer w4: U3.B2 818.09,734.94 876.28,734.94 C14.2 ; C14.2@890.35,725 C14.2 ; X1.1 927.64,744.29 922.77,739.42 902.32,739.42 887.9,725 C14.2
XC2: C11.2 U3.A1 X1.3 | length 110.3
  Top Layer w5: C11.2 855.04,796.22
  Top Layer w6: U3.A1 845,761.85 C11.2 ; 855.04,796.22 X1.3
pads on no net: E1.2 U3.B6 U3.C3 U3.C7 U3.D7 U4.1 U4.2 U4.3 U4.4 U4.5 U4.6 U4.7 U4.11 U4.14 U4.15 U4.16 U4.17 U4.21 U5.2 U5.3 U5.5 U5.10 U5.15 U8.4

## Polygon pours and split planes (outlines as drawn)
GND on Bottom Layer "Top Layer-No Net" (solid, remove dead copper, pour order 2): -39.37,1015.75 996.06,1015.75 996.06,19.68 1059.06,-43.31 1047.24,-55.12 15.75,-55.12 -39.37,-55.12 -74.8,-19.68 -59.06,-3.94 -59.06,885.83 -59.06,992.13 -39.37,1011.81 -39.37,1015.75 -31.5,1023.62
GND on Top Layer "Top Layer-No Net" (solid, remove dead copper, pour order 4): -39.37,1035.43 -27.56,1047.24 1039.37,1047.24 1039.37,11.81 1019.68,-7.87 984.25,-43.31 23.62,-43.31 -3.94,-43.31 -43.31,-3.94 -74.8,27.56 -74.8,925.2 -74.8,996.06 -35.43,1035.43

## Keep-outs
Keep-Out Layer:
  circle w3.94: c59.06,929.13 r19.68
  circle w3.94: c925.2,55.12 r19.68
  lines w3.94: 0,23.62 ccw(c23.62,23.62) 23.62,0 960.63,0 ccw(c960.63,23.62) 984.25,23.62 984.25,960.63 ccw(c960.63,960.63) 960.63,984.25 23.62,984.25 ccw(c23.62,960.63) 0,960.63 0,23.62

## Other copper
Top Layer:
  rectangle net VBUS: 31.5,370.08 82.68,566.93
  rectangle net VBUS: 35.43,370.08 137.8,405.51
  rectangle net NetD3_1: 43.31,244.09 133.86,283.46
  rectangle net GND: 98.43,27.56 145.67,196.85
  rectangle net COIL1: 39.37,27.56 86.61,196.85
  pour cut-out: 859.25,849.95 953.35,849.95 953.35,736.94 859.05,736.94
  pour cut-out: 799.21,208.66 968.5,208.66 972.44,212.6 972.44,444.88 956.69,460.63 846.46,460.63 834.65,448.82 834.65,326.77 799.21,291.34
  pour cut-out: 761.81,900 792.91,900 792.91,736.61 792.13,735.83 761.81,735.83 761.81,888.19
Multi-Layer:
  pour cut-out: 740.94,982.68 987.01,982.68 987.01,889.76 982.28,885.04 739.76,885.04 739.76,981.5

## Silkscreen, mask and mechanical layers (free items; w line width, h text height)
Top Solder:
  rectangle: 102.36,27.56 145.67,70.87
  rectangle: 39.37,27.56 82.68,70.87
